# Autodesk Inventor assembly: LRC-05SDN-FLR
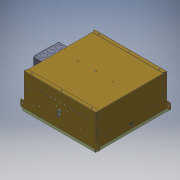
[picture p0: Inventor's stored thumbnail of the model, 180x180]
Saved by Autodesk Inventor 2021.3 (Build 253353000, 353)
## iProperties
Part Number: LRC-05SDN-FLR
Document SubType Name: Assembly
Designer: JChurch
description: 0:0:Super Shallow 5-6" Downlight - COB LED
manufacturer: 0:0:The Kirlin Company
model: 0:0:LRC-05SDN
url: 0:0:
load_classification: Lighting
motor: 0 ul
Author: JChurch
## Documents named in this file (6)
- X:\Revit Files\0000-Un-Zipped\COB\LRC-05SDN-FLR\LRC-05SDN-FLR.iam
- X:\INVENTOR\830\830399-00-00.ipt
- X:\INVENTOR\881\881088-00-00.iam
- X:\INVENTOR\KIRLIN_ENG\750\750032-00-XX.iam
- X:\INVENTOR\725\725377-00-00.ipt
- X:\Revit Files\0000-Un-Zipped\COB\LRC-05SDN-FLR\LRC-05SDN-FLR_Substitute_1.ipt
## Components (5 placed, 5 different names)
1. 830399-00-00:1 — Mate:1, Mate:2, Mate:3, Mate:4, Tangent:1, Angle:1, Insert:2
2. 881088-00-00:1 [sub-assembly] — Mate:4, Tangent:1, Angle:1
3. 750032-00-XX:1 [sub-assembly] — Insert:1, Insert:2
4. 725377-00-00:1 — Insert:1
5. LRC-05SDN-FLR_Substitute_1:1
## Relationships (8: Mate 4, Insert 2, Tangent 1, Angle 1)
- Mate:1: 830399-00-00:1
- Mate:2: 830399-00-00:1
- Mate:3: 830399-00-00:1
- Mate:4: 830399-00-00:1 ↔ 881088-00-00:1
- Tangent:1: 830399-00-00:1 ↔ 881088-00-00:1
- Angle:1: 830399-00-00:1 ↔ 881088-00-00:1
- Insert:1: 750032-00-XX:1 ↔ 725377-00-00:1
- Insert:2: 830399-00-00:1 ↔ 750032-00-XX:1
